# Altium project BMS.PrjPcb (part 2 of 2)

## Sheet BQ7721606.SchDoc
size A3; SheetNumber: 8; SheetTotal: 10
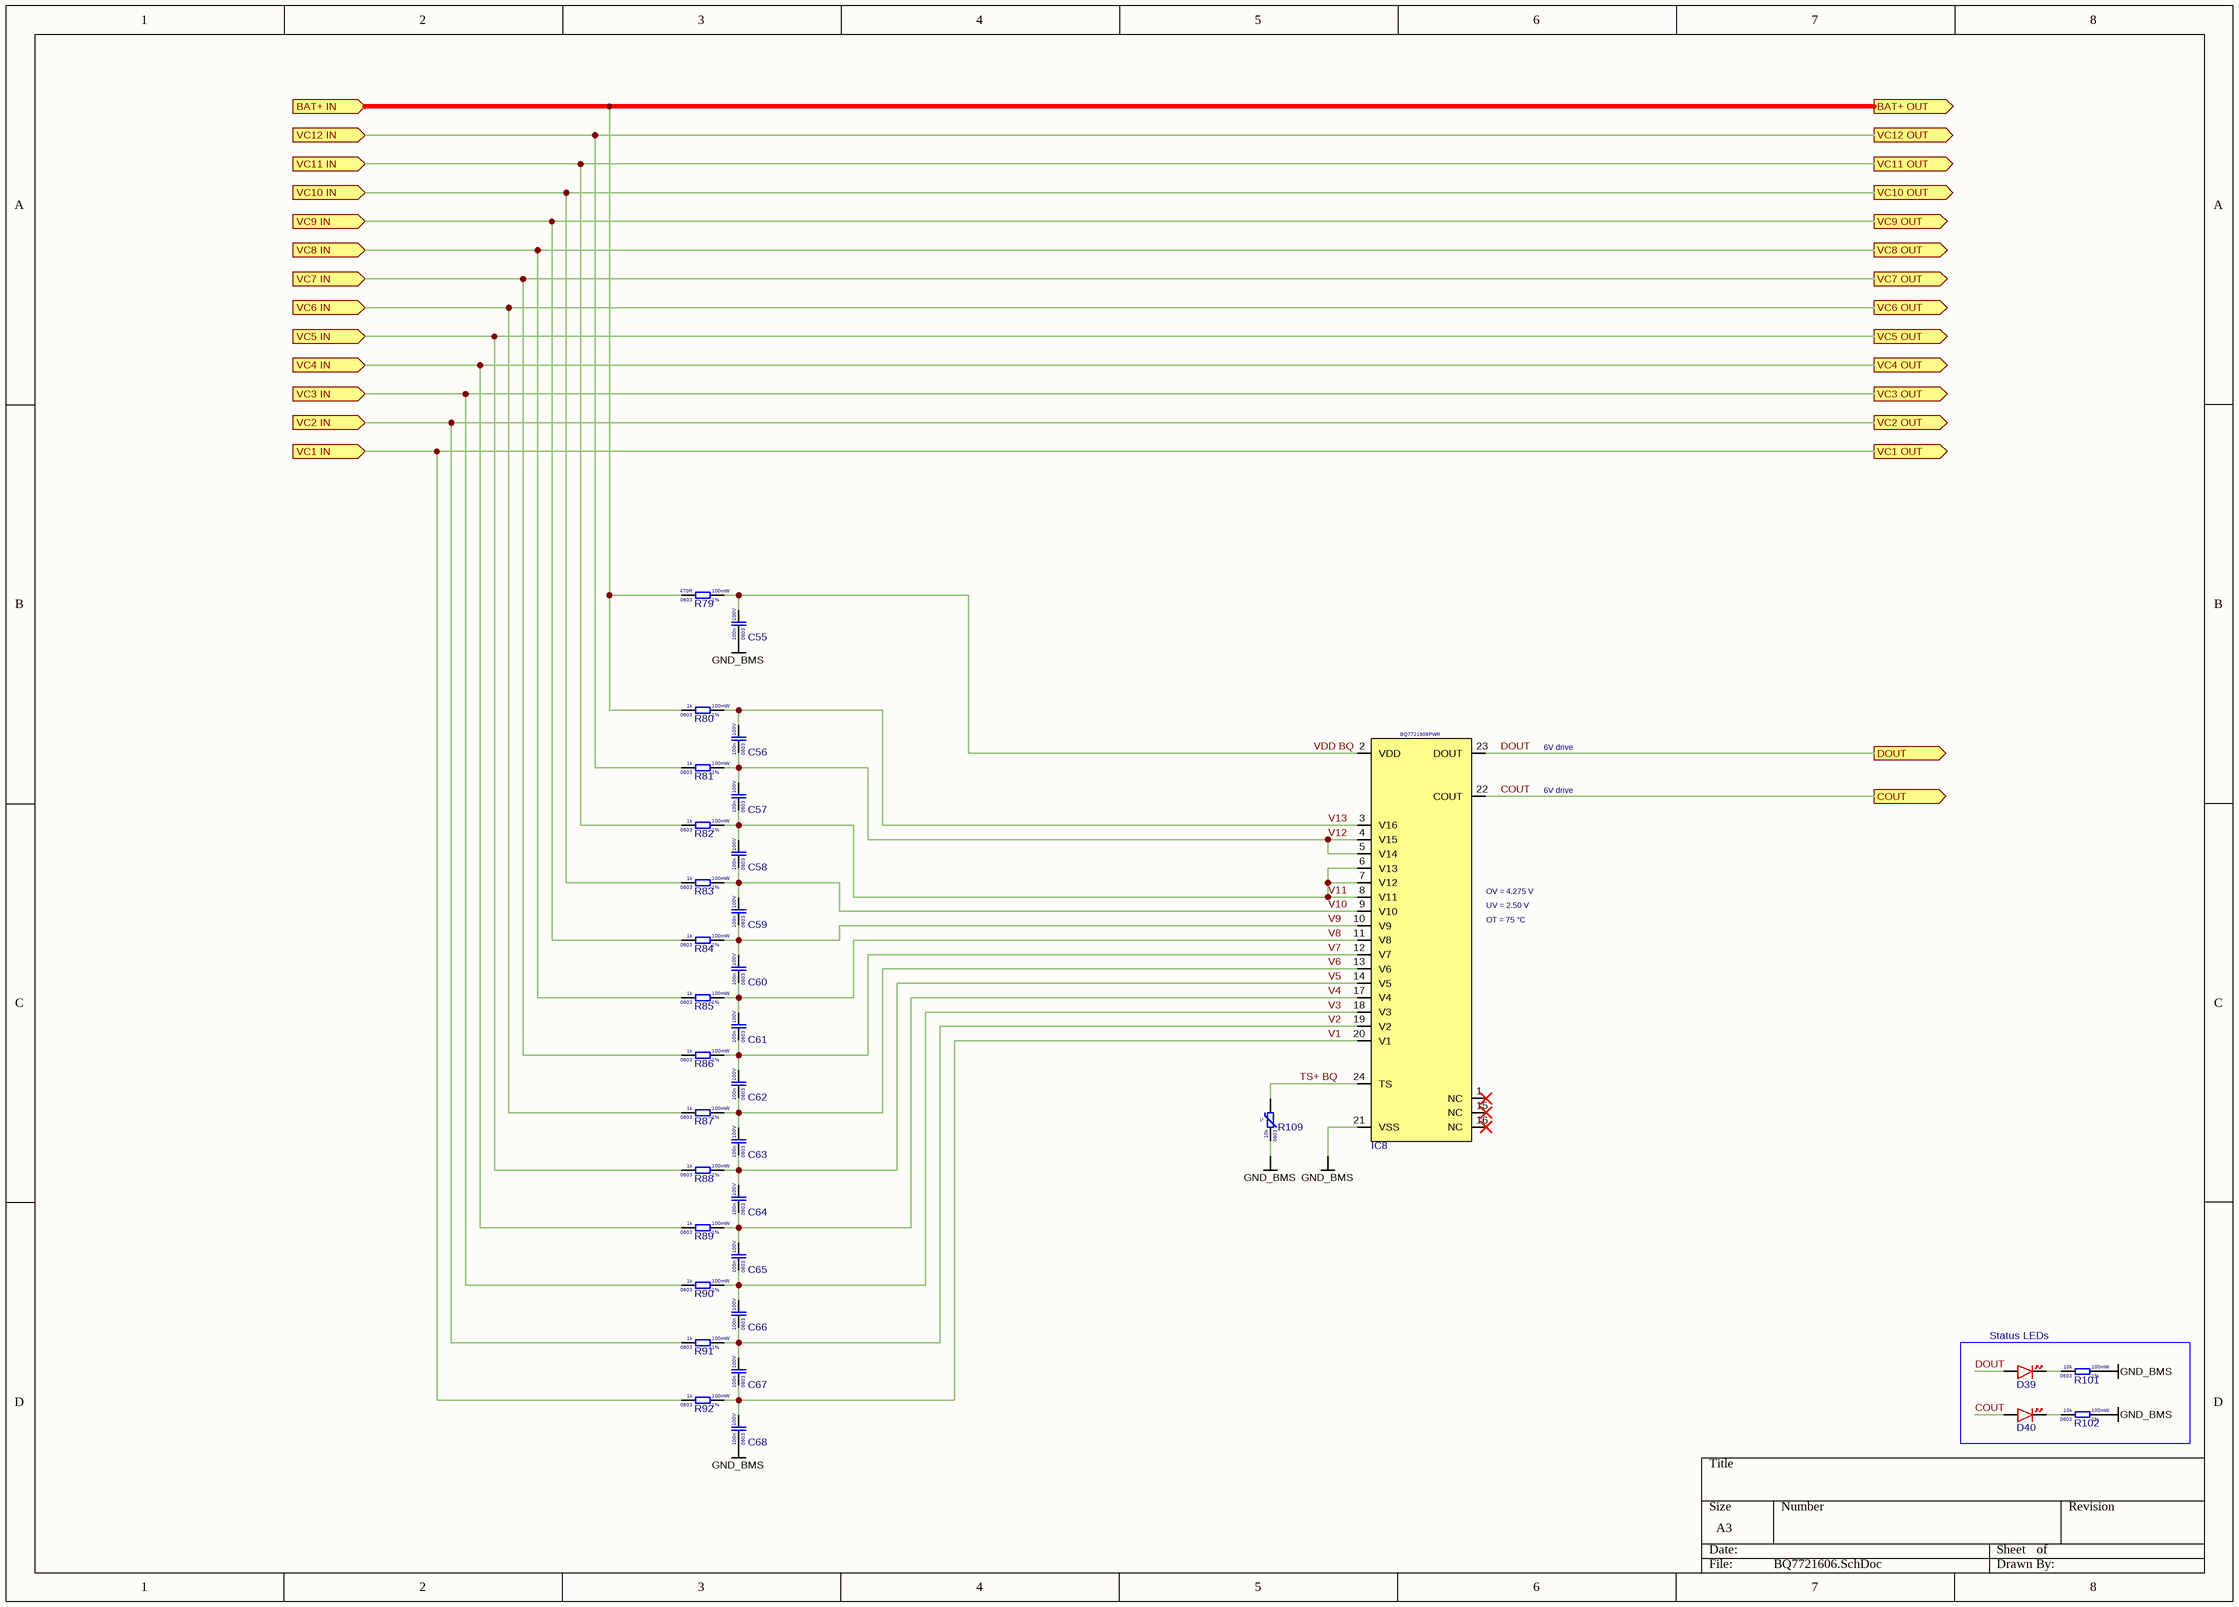
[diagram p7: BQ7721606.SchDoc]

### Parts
C55  Voltage Rating: 100V  Case Code (Imperial): 0603  Capacitance: 100n  [CAP 0603]  (hidden comment: CC0603KRX7R0BB104)
C56  Voltage Rating: 100V  Case Code (Imperial): 0603  Capacitance: 100n  [CAP 0603]  (hidden comment: CC0603KRX7R0BB104)
C57  Voltage Rating: 100V  Case Code (Imperial): 0603  Capacitance: 100n  [CAP 0603]  (hidden comment: CC0603KRX7R0BB104)
C58  Voltage Rating: 100V  Case Code (Imperial): 0603  Capacitance: 100n  [CAP 0603]  (hidden comment: CC0603KRX7R0BB104)
C59  Voltage Rating: 100V  Case Code (Imperial): 0603  Capacitance: 100n  [CAP 0603]  (hidden comment: CC0603KRX7R0BB104)
C60  Voltage Rating: 100V  Case Code (Imperial): 0603  Capacitance: 100n  [CAP 0603]  (hidden comment: CC0603KRX7R0BB104)
C61  Voltage Rating: 100V  Case Code (Imperial): 0603  Capacitance: 100n  [CAP 0603]  (hidden comment: CC0603KRX7R0BB104)
C62  Voltage Rating: 100V  Case Code (Imperial): 0603  Capacitance: 100n  [CAP 0603]  (hidden comment: CC0603KRX7R0BB104)
C63  Voltage Rating: 100V  Case Code (Imperial): 0603  Capacitance: 100n  [CAP 0603]  (hidden comment: CC0603KRX7R0BB104)
C64  Voltage Rating: 100V  Case Code (Imperial): 0603  Capacitance: 100n  [CAP 0603]  (hidden comment: CC0603KRX7R0BB104)
C65  Voltage Rating: 100V  Case Code (Imperial): 0603  Capacitance: 100n  [CAP 0603]  (hidden comment: CC0603KRX7R0BB104)
C66  Voltage Rating: 100V  Case Code (Imperial): 0603  Capacitance: 100n  [CAP 0603]  (hidden comment: CC0603KRX7R0BB104)
C67  Voltage Rating: 100V  Case Code (Imperial): 0603  Capacitance: 100n  [CAP 0603]  (hidden comment: CC0603KRX7R0BB104)
C68  Voltage Rating: 100V  Case Code (Imperial): 0603  Capacitance: 100n  [CAP 0603]  (hidden comment: CC0603KRX7R0BB104)
D39  XL-1608SURC-06  [DIODE_0603_RED]  (value not drawn)
D40  XL-1608SURC-06  [DIODE_0603_RED]  (value not drawn)
IC8  BQ7721606PWR  [TSSOP-24]
R79  Resistance Tolerance: 1%  Resistance: 470R  Power Rating: 100mW  Case Code (Imperial): 0603  [RES_0603]  (hidden comment: 0603WAF4700T5E)
R80  Resistance Tolerance: 1%  Resistance: 1k  Power Rating: 100mW  Case Code (Imperial): 0603  [RES_0603]  (hidden comment: 0603WAF1001T5E)
R81  Resistance Tolerance: 1%  Resistance: 1k  Power Rating: 100mW  Case Code (Imperial): 0603  [RES_0603]  (hidden comment: 0603WAF1001T5E)
R82  Resistance Tolerance: 1%  Resistance: 1k  Power Rating: 100mW  Case Code (Imperial): 0603  [RES_0603]  (hidden comment: 0603WAF1001T5E)
R83  Resistance Tolerance: 1%  Resistance: 1k  Power Rating: 100mW  Case Code (Imperial): 0603  [RES_0603]  (hidden comment: 0603WAF1001T5E)
R84  Resistance Tolerance: 1%  Resistance: 1k  Power Rating: 100mW  Case Code (Imperial): 0603  [RES_0603]  (hidden comment: 0603WAF1001T5E)
R85  Resistance Tolerance: 1%  Resistance: 1k  Power Rating: 100mW  Case Code (Imperial): 0603  [RES_0603]  (hidden comment: 0603WAF1001T5E)
R86  Resistance Tolerance: 1%  Resistance: 1k  Power Rating: 100mW  Case Code (Imperial): 0603  [RES_0603]  (hidden comment: 0603WAF1001T5E)
R87  Resistance Tolerance: 1%  Resistance: 1k  Power Rating: 100mW  Case Code (Imperial): 0603  [RES_0603]  (hidden comment: 0603WAF1001T5E)
R88  Resistance Tolerance: 1%  Resistance: 1k  Power Rating: 100mW  Case Code (Imperial): 0603  [RES_0603]  (hidden comment: 0603WAF1001T5E)
R89  Resistance Tolerance: 1%  Resistance: 1k  Power Rating: 100mW  Case Code (Imperial): 0603  [RES_0603]  (hidden comment: 0603WAF1001T5E)
R90  Resistance Tolerance: 1%  Resistance: 1k  Power Rating: 100mW  Case Code (Imperial): 0603  [RES_0603]  (hidden comment: 0603WAF1001T5E)
R91  Resistance Tolerance: 1%  Resistance: 1k  Power Rating: 100mW  Case Code (Imperial): 0603  [RES_0603]  (hidden comment: 0603WAF1001T5E)
R92  Resistance Tolerance: 1%  Resistance: 1k  Power Rating: 100mW  Case Code (Imperial): 0603  [RES_0603]  (hidden comment: 0603WAF1001T5E)
R101  Resistance Tolerance: 1%  Resistance: 10k  Power Rating: 100mW  Case Code (Imperial): 0603  [RES_0603]  (hidden comment: 0603WAF1002T5E)
R102  Resistance Tolerance: 1%  Resistance: 10k  Power Rating: 100mW  Case Code (Imperial): 0603  [RES_0603]  (hidden comment: 0603WAF1002T5E)
R109  Resistance: 10k  Case Code (Imperial): 0603  [RES_0603]  (hidden comment: NCP18XH103F03RB)

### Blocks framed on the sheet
Status LEDs: D39 D40 R101 R102

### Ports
BAT+ IN (in, see BMS[1A]), BAT+ OUT (out, see BMS[2A]), COUT (out, see BMS[2A], BQ76952 BMS[3A], MCU[1B]), DOUT (out, see BMS[2A], BQ76952 BMS[3A], MCU[1A]), VC1 IN (in, see BMS[1B]), VC1 OUT (out, see BMS[2B]), VC2 IN (in, see BMS[1B]), VC2 OUT (out, see BMS[2B]), VC3 IN (in, see BMS[1B]), VC3 OUT (out, see BMS[2B]), VC4 IN (in, see BMS[1B]), VC4 OUT (out, see BMS[2B]), VC5 IN (in, see BMS[1B]), VC5 OUT (out, see BMS[2B]), VC6 IN (in, see BMS[1B]), VC6 OUT (out, see BMS[2B]), VC7 IN (in, see BMS[1B]), VC7 OUT (out, see BMS[2B]), VC8 IN (in, see BMS[1B]), VC8 OUT (out, see BMS[2B]), VC9 IN (in, see BMS[1B]), VC9 OUT (out, see BMS[2B]), VC10 IN (in, see BMS[1B]), VC10 OUT (out, see BMS[2B]), VC11 IN (in, see BMS[1B]), VC11 OUT (out, see BMS[2B]), VC12 IN (in, see BMS[1B]), VC12 OUT (out, see BMS[2B])

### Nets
GND_BMS: C55.1 C68.1 IC8.21(VSS) R101.2 R102.2 R109.1
BAT+: R79.1 R80.1 ; port BAT+ IN, port BAT+ OUT
C1: R92.1 ; port VC1 IN, port VC1 OUT
C2: R91.1 ; port VC2 IN, port VC2 OUT
C3: R90.1 ; port VC3 IN, port VC3 OUT
C4: R89.1 ; port VC4 IN, port VC4 OUT
C5: R88.1 ; port VC5 IN, port VC5 OUT
C6: R87.1 ; port VC6 IN, port VC6 OUT
C7: R86.1 ; port VC7 IN, port VC7 OUT
C8: R85.1 ; port VC8 IN, port VC8 OUT
C9: R84.1 ; port VC9 IN, port VC9 OUT
C10: R83.1 ; port VC10 IN, port VC10 OUT
C11: R82.1 ; port VC11 IN, port VC11 OUT
C12: R81.1 ; port VC12 IN, port VC12 OUT
COUT: D40.A IC8.22(COUT) ; port COUT
DOUT: D39.A IC8.23(DOUT) ; port DOUT
TS+ BQ: IC8.24(TS) R109.2
V1: C67.1 C68.2 IC8.20(V1) R92.2
V2: C66.1 C67.2 IC8.19(V2) R91.2
V3: C65.1 C66.2 IC8.18(V3) R90.2
V4: C64.1 C65.2 IC8.17(V4) R89.2
V5: C63.1 C64.2 IC8.14(V5) R88.2
V6: C62.1 C63.2 IC8.13(V6) R87.2
V7: C61.1 C62.2 IC8.12(V7) R86.2
V8: C60.1 C61.2 IC8.11(V8) R85.2
V9: C59.1 C60.2 IC8.10(V9) R84.2
V10: C58.1 C59.2 IC8.9(V10) R83.2
V11: C57.1 C58.2 IC8.6(V13) IC8.7(V12) IC8.8(V11) R82.2
V12: C56.1 C57.2 IC8.4(V15) IC8.5(V14) R81.2
V13: C56.2 IC8.3(V16) R80.2
VDD BQ: C55.2 IC8.2(VDD) R79.2
NetD39_K: D39.K R101.1
NetD40_K: D40.K R102.1

Not connected (* = marked no-connect by the designer): IC8 1(NC)* 15(NC)* 16(NC)*

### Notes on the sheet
- 6V drive
- (near IC8) OV = 4.275 V
- (near IC8) UV = 2.50 V
- (near IC8) OT = 75 °C

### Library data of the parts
C55-C68 = CC0603KRX7R0BB104: Cap 100nF 100V 0603 X7R; Manufacturer: YAGEO
D39 D40 = XL-1608SURC-06: LED Red 0603 25mA; Manufacturer: Xinglight
IC8 = BQ7721606PWR: BMS Secondary protector IC 3~16s; Manufacturer: Texas Instruments
R79 = 0603WAF4700T5E: Res 470R 0603 1% 100mW 75V; Manufacturer: Uni-Royal
R80-R92 = 0603WAF1001T5E: Res 1k 0603 1% 100mW 75V; Manufacturer: Uni-Royal
R101 R102 = 0603WAF1002T5E: Res 10k 0603 1% 100mW 75V; Manufacturer: Uni-Royal
R109 = NCP18XH103F03RB: NTC 10k 0603 1% 3455K; Manufacturer: Murata

## Sheet ESD system side.SchDoc
size A3; SheetNumber: 8; SheetTotal: 9
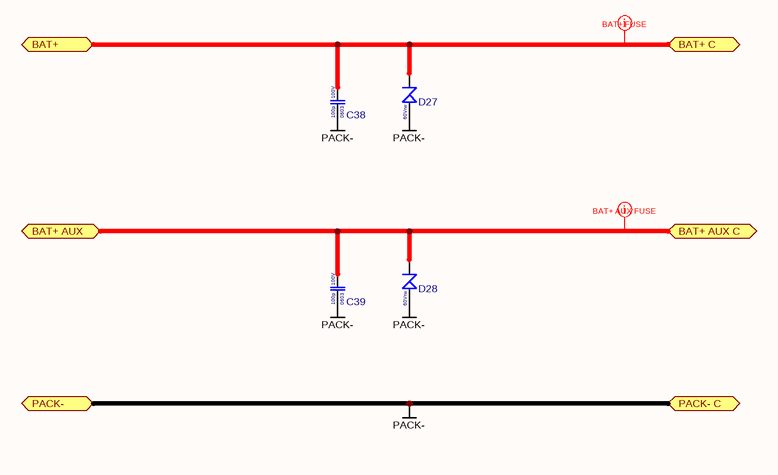
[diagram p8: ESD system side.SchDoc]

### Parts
C38  Voltage Rating: 100V  Case Code (Imperial): 0603  Capacitance: 100p  [CAP 0603]  (hidden comment: CC0603JRNPO0BN101)
C39  Voltage Rating: 100V  Case Code (Imperial): 0603  Capacitance: 100p  [CAP 0603]  (hidden comment: CC0603JRNPO0BN101)
D27  Reverse Voltage: 60Vrw  [DO-214AA]  (hidden comment: SMBJ60A)
D28  Reverse Voltage: 60Vrw  [DO-214AA]  (hidden comment: SMBJ60A)

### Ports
BAT+ (bidir, see BMS Arhitecture[6A]), BAT+ AUX (bidir, see BMS Arhitecture[6A]), BAT+ AUX C (bidir, see BMS Arhitecture[7A]), BAT+ C (bidir, see BMS Arhitecture[7A]), PACK- (bidir, see BMS Arhitecture[6C], BMS[8D]), PACK- C (bidir, see BMS Arhitecture[7C])

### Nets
PACK-: C38.1 C39.1 D27.A D28.A ; port PACK- C, port PACK-
NetC38_2: C38.2 D27.K ; port BAT+ C, port BAT+
NetC39_2: C39.2 D28.K ; port BAT+ AUX, port BAT+ AUX C

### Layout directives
net class BAT+ FUSE: NetC38_2
net class BAT+ AUX FUSE: NetC39_2

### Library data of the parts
C38 C39 = CC0603JRNPO0BN101: Cap 100pF 100V 0603 NP0; Manufacturer: Yageo; Manufacturer Part Number: CC0603KRX7R9BB104
D27 D28 = SMBJ60A: TVS ESD Zener UniD 60Vrw 1uA; Manufacturer: Shandong Jingdao Microelectronics

## Sheet ESD battery side.SchDoc
size A3; SheetNumber: 10; SheetTotal: 10
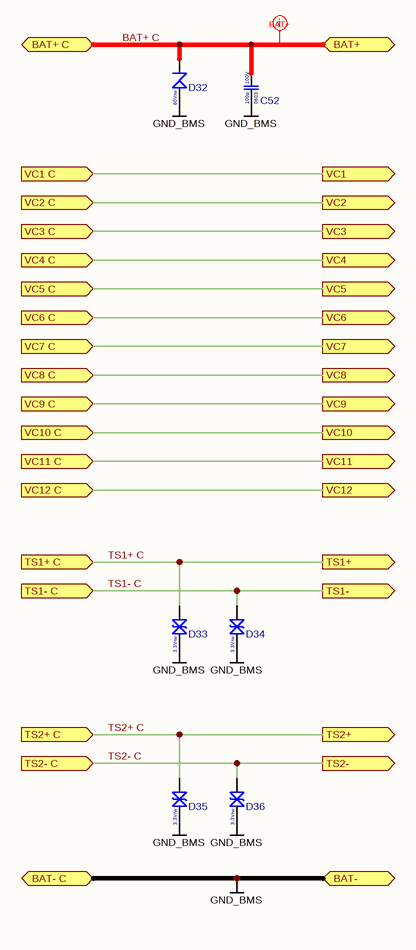
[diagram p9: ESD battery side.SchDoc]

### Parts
C52  Voltage Rating: 100V  Case Code (Imperial): 0603  Capacitance: 100p  [CAP 0603]  (hidden comment: CC0603JRNPO0BN101)
D32  Reverse Voltage: 60Vrw  [DO-214AA]  (hidden comment: SMBJ60A)
D33  V_RWM: 3.3Vrw  [SOD-523]  (hidden comment: H3V3LD5B)
D34  V_RWM: 3.3Vrw  [SOD-523]  (hidden comment: H3V3LD5B)
D35  V_RWM: 3.3Vrw  [SOD-523]  (hidden comment: H3V3LD5B)
D36  V_RWM: 3.3Vrw  [SOD-523]  (hidden comment: H3V3LD5B)

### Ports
BAT+ (bidir, see BMS Arhitecture[2B]), BAT+ C (bidir, see BMS Arhitecture[2B]), BAT- (bidir, see BMS Arhitecture[2C], BMS[1D]), BAT- C (bidir, see BMS Arhitecture[2C]), TS1+ (out, see BMS Arhitecture[2B]), TS1+ C (in, see BMS Arhitecture[2B]), TS1- (out, see BMS Arhitecture[2B]), TS1- C (in, see BMS Arhitecture[2B]), TS2+ (out, see BMS Arhitecture[2C], BMS[1C], BQ76952 BMS[3C]), TS2+ C (in, see BMS Arhitecture[2C]), TS2- (out, see BMS Arhitecture[2C], BMS[1C], BQ76952 BMS[3C]), TS2- C (in, see BMS Arhitecture[2C]), VC1 (out, see BMS Arhitecture[2B], BMS[1B], BQ76952 BMS[1C]), VC1 C (in, see BMS Arhitecture[2B]), VC2 (out, see BMS Arhitecture[2B], BMS[1B], BQ76952 BMS[1C]), VC2 C (in, see BMS Arhitecture[2B]), VC3 (out, see BMS Arhitecture[2B], BMS[1B], BQ76952 BMS[1C]), VC3 C (in, see BMS Arhitecture[2B]), VC4 (out, see BMS Arhitecture[2B], BMS[1B], BQ76952 BMS[1C]), VC4 C (in, see BMS Arhitecture[2B]), VC5 (out, see BMS Arhitecture[2B], BMS[1B], BQ76952 BMS[1C]), VC5 C (in, see BMS Arhitecture[2B]), VC6 (out, see BMS Arhitecture[2B], BMS[1B], BQ76952 BMS[1C]), VC6 C (in, see BMS Arhitecture[2B]), VC7 (out, see BMS Arhitecture[2B], BMS[1B], BQ76952 BMS[1C]), VC7 C (in, see BMS Arhitecture[2B]), VC8 (out, see BMS Arhitecture[2B], BMS[1B], BQ76952 BMS[1B]), VC8 C (in, see BMS Arhitecture[2B]), VC9 (out, see BMS Arhitecture[2B], BMS[1B], BQ76952 BMS[1B]), VC9 C (in, see BMS Arhitecture[2B]), VC10 (out, see BMS Arhitecture[2B], BMS[1B], BQ76952 BMS[1B]), VC10 C (in, see BMS Arhitecture[2B]), VC11 (out, see BMS Arhitecture[2B], BMS[1B], BQ76952 BMS[1B]), VC11 C (in, see BMS Arhitecture[2B]), VC12 (out, see BMS Arhitecture[2B], BMS[1B], BQ76952 BMS[1B]), VC12 C (in, see BMS Arhitecture[2B])

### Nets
GND_BMS: C52.1 D32.A D33.K D34.K D35.K D36.K ; port BAT- C, port BAT-
BAT+ C: C52.2 D32.K ; port BAT+ C, port BAT+
C1: port VC1 C, port VC1
C2: port VC2 C, port VC2
C3: port VC3 C, port VC3
C4: port VC4 C, port VC4
C5: port VC5 C, port VC5
C6: port VC6 C, port VC6
C7: port VC7 C, port VC7
C8: port VC8 C, port VC8
C9: port VC9 C, port VC9
C10: port VC10 C, port VC10
C11: port VC11 C, port VC11
C12: port VC12 C, port VC12
TS1+ C: D33.A ; port TS1+ C, port TS1+
TS1- C: D34.A ; port TS1- C, port TS1-
TS2+ C: D35.A ; port TS2+ C, port TS2+  [project net TS1]
TS2- C: D36.A ; port TS2- C, port TS2-

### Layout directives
net class BAT+: BAT+ C

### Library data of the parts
C52 = CC0603JRNPO0BN101: as C38 on sheet ESD system side
D32 = SMBJ60A: as D27 on sheet ESD system side
D33-D36 = H3V3LD5B: ESD TVS 3.3Vrw 0.2uA 12.5pF; Manufacturer: hongjiacheng

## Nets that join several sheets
5V BMS: BMS Arhitecture (X7.4), BMS (D6.K), BAT+ to 5V1 STEP-DOWN (6 pins), 5V to 3V3 LDO (C45.2 IC6.2)
GND_BMS: BMS Arhitecture (15 pins), BMS (NT1.1 R1.1), BQ76952 BMS (32 pins), BQ34Z100 FUEL GAUGE (10 pins), MCU (18 pins), BAT+ to 5V1 STEP-DOWN (8 pins), 5V to 3V3 LDO (6 pins), BQ7721606 (6 pins), ESD battery side (6 pins)
PACK-: BMS Arhitecture (MH2.1 X1.- X1.CASE X2.2), BMS (NT2.1 R1.2), ESD system side (C38.1 C39.1 D27.A D28.A)
VDD: BMS Arhitecture (X8.1), BQ34Z100 FUEL GAUGE (C47.2 IC7.5 IC7.6), MCU (6 pins), 5V to 3V3 LDO (C46.2 D31.A IC6.3)
ALRT: BQ76952 BMS (R31.2), MCU (IC4.16)
BAT+: BMS Arhitecture (F1.1 F2.1 F3.2), BQ76952 BMS (7 pins), BQ34Z100 FUEL GAUGE (Q5.S R68.2), BAT+ to 5V1 STEP-DOWN (D29.A), BQ7721606 (R79.1 R80.1)
BAT+ C: BMS Arhitecture (F3.1 X3.1), ESD battery side (C52.2 D32.K)
C1: BMS Arhitecture (X4.1), BQ76952 BMS (R33.1), BQ7721606 (R92.1)
C2: BMS Arhitecture (X4.2), BQ76952 BMS (R30.1), BQ7721606 (R91.1)
C3: BMS Arhitecture (X4.3), BQ76952 BMS (R28.1), BQ7721606 (R90.1)
C4: BMS Arhitecture (X4.4), BQ76952 BMS (R26.1), BQ7721606 (R89.1)
C5: BMS Arhitecture (X4.5), BQ76952 BMS (R25.1), BQ7721606 (R88.1)
C6: BMS Arhitecture (X4.6), BQ76952 BMS (R24.1), BQ7721606 (R87.1)
C7: BMS Arhitecture (X4.7), BQ76952 BMS (R23.1), BQ7721606 (R86.1)
C8: BMS Arhitecture (X4.8), BQ76952 BMS (R22.1), BQ7721606 (R85.1)
C9: BMS Arhitecture (X4.9), BQ76952 BMS (R21.1), BQ7721606 (R84.1)
C10: BMS Arhitecture (X4.10), BQ76952 BMS (R20.1), BQ7721606 (R83.1)
C11: BMS Arhitecture (X4.11), BQ76952 BMS (R18.1), BQ7721606 (R82.1)
C12: BMS Arhitecture (X4.12), BQ76952 BMS (R14.1), BQ7721606 (R81.1)
CAN RX: BMS Arhitecture (X7.1), MCU (IC4.47 X15.1)
CAN TX: BMS Arhitecture (X7.2), MCU (R38.2 X16.1)
CFETOFF: BQ76952 BMS (IC1.29), MCU (IC4.19)
COUT: BQ76952 BMS (R100.1), MCU (D38.A), BQ7721606 (D40.A IC8.22)
DCDC EN: MCU (D18.A R44.1), BAT+ to 5V1 STEP-DOWN (IC5.3)
DFETOFF: BQ76952 BMS (IC1.30), MCU (IC4.18)
DOUT: BQ76952 BMS (R98.1), MCU (D37.A), BQ7721606 (D39.A IC8.23)
NetC38_2: BMS Arhitecture (F1.2 X1.+), ESD system side (C38.2 D27.K)
NetC39_2: BMS Arhitecture (F2.2 X2.1), ESD system side (C39.2 D28.K)
NetF3_3: BMS Arhitecture (F3.3), BQ76952 BMS (Q9.D)
NetNT1_2: BMS (NT1.2), BQ76952 BMS (R36.1), BQ34Z100 FUEL GAUGE (R74.1)
NetNT2_2: BMS (NT2.2), BQ76952 BMS (R37.1), BQ34Z100 FUEL GAUGE (R75.1)
nRST: BMS Arhitecture (D3.K X8.10), MCU (C37.2 IC4.4 R52.1)
PACK+: BMS Arhitecture (MH1.1), BQ76952 BMS (9 pins)
REG1: BMS (D6.A), BQ76952 BMS (C15.2 D43.A IC1.35)
RST/SHUT: BQ76952 BMS (R32.2), MCU (IC4.17)
SCLt: BMS Arhitecture (D5.K X7.9 X10.2), BQ76952 BMS (R29.2), BQ34Z100 FUEL GAUGE (R73.2), MCU (R45.1 R47.1)
SDAt: BMS Arhitecture (D4.K X7.8 X10.1), BQ76952 BMS (R27.2), BQ34Z100 FUEL GAUGE (R71.2), MCU (R46.1 R48.1)
SWCLK: BMS Arhitecture (D2.K X8.4), MCU (R50.2)
SWDIO: BMS Arhitecture (D1.K X8.2), MCU (R49.2)
TS1: BMS Arhitecture (X4.15), BQ76952 BMS (C20.2 IC1.21), ESD battery side (D35.A)
TS1+ C: BMS Arhitecture (X4.13 X7.5), ESD battery side (D33.A)
TS1- C: BMS Arhitecture (X4.14 X7.6), ESD battery side (D34.A)
TS2- C: BMS Arhitecture (X4.16), BQ76952 BMS (NT3.1), ESD battery side (D36.A)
